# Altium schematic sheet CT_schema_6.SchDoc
size 371 x 245 mm
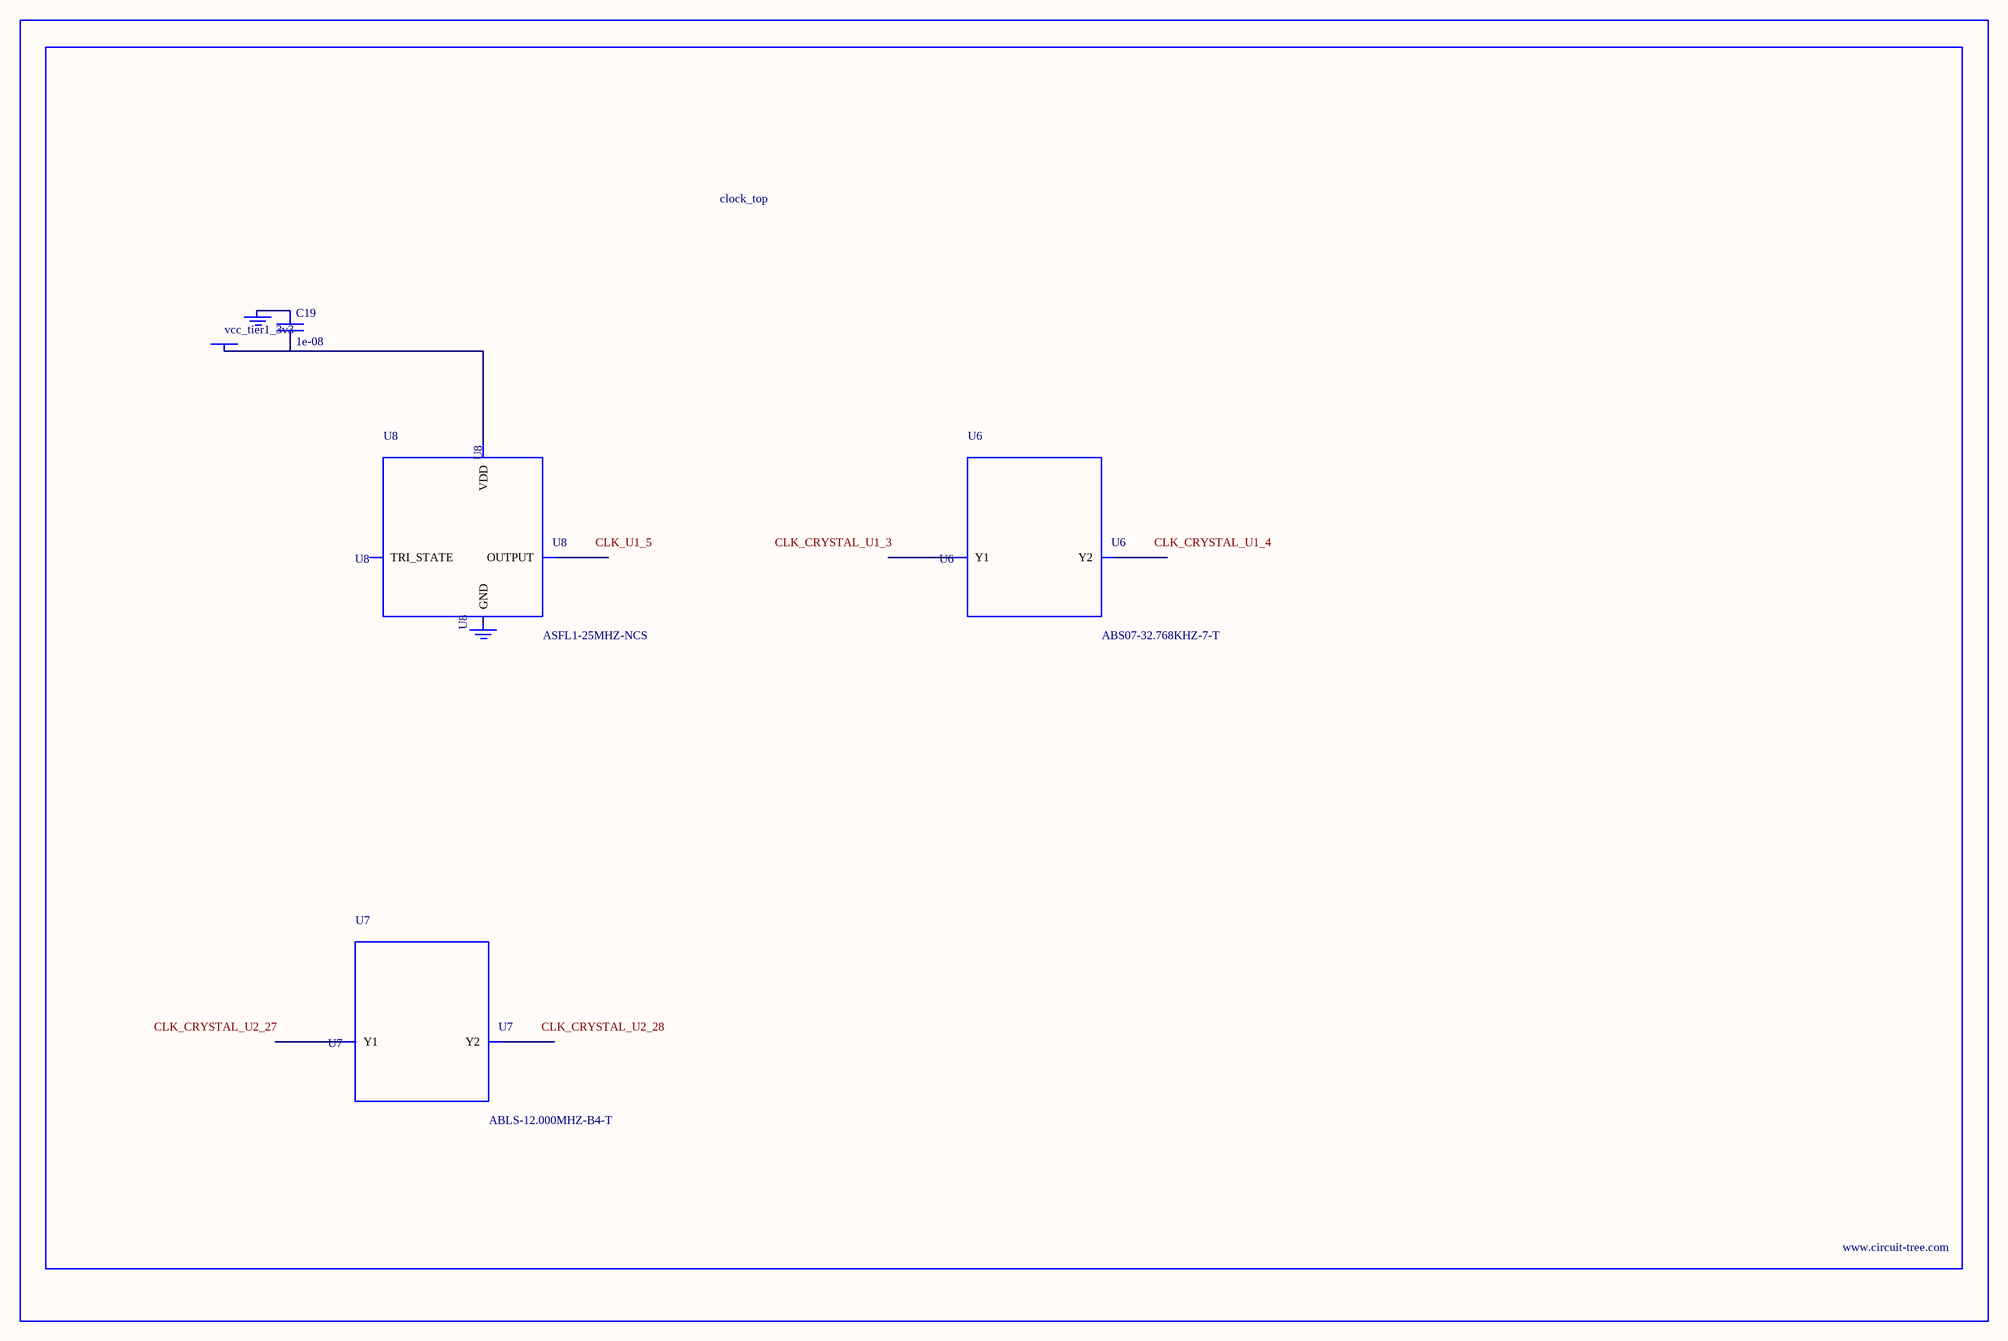
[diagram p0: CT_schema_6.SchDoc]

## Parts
BORDER5  (no value)
C19  1e-08  [C0402]
GND_INSTANCE_5_0  (no value)
GND_INSTANCE_5_1  (no value)
POWER_INSTANCE_5_0  vcc_tier1_3v3
U6  ABS07-32.768KHZ-7-T  [ABS07-32.768KHZ-7-T]
U7  ABLS-12.000MHZ-B4-T  [ABLS-12.000MHZ-B4-T]
U8  ASFL1-25MHZ-NCS  [ASFL1]

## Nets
NetC19_1: C19.1 GND_INSTANCE_5_0.0(GND)
NetC19_2: C19.2 POWER_INSTANCE_5_0.0(PWR) U8.4(VDD)

Not connected (* = marked no-connect by the designer): GND_INSTANCE_5_1 0(GND); U6 1(Y1) 2(Y2); U7 1(Y1) 2(Y2); U8 1(TRI_STATE) 2(GND) 3(OUTPUT)

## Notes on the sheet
- Labels drawn without touching a wire or pin: CLK_CRYSTAL_U1_3, CLK_CRYSTAL_U1_4, CLK_CRYSTAL_U2_27, CLK_CRYSTAL_U2_28, CLK_U1_5

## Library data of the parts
BORDER5 = BORDER_PAGE5
C19 = C0402C103K3RAC
GND_INSTANCE_5_0 GND_INSTANCE_5_1 = GND
POWER_INSTANCE_5_0 = PWR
